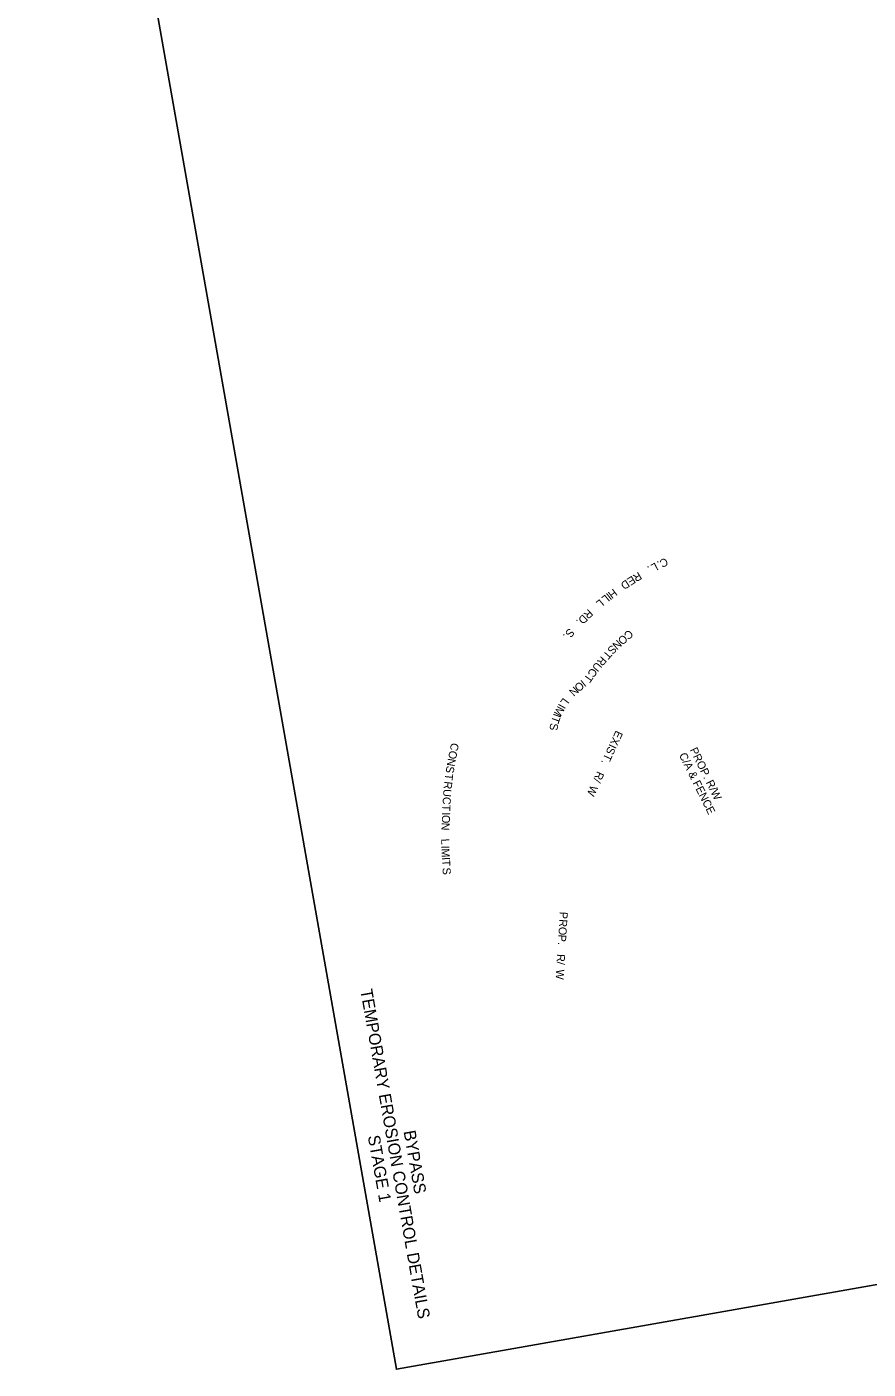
# Model space of a CAD drawing. Extents: x 979945 to 981206, y 1838799 to 1840551.
# Drawn here: x 979945 to 980575, y 1838799 to 1839805 of the extents above; entities that cross this region are included whole.
import ezdxf

# ---------------------------------------------------------------- set-up
doc = ezdxf.new("R2010")
doc.units = 0
for name, color, linetype in [('60', 7, 'Continuous'), ('Default', 7, 'Continuous'), ('R_Draft', 7, 'Continuous')]:
    doc.layers.add(name, color=color, linetype=linetype)

msp = doc.modelspace()

# ---------------------------------------------------------------- linework, layer by layer
at = {"layer": 'Default'}
msp.add_lwpolyline([(979944.5, 1840369.9), (980971, 1840550.9), (981196.2, 1839273.6), (981147.4, 1839265), (981177.1, 1839096.8), (981031.8, 1839071.2), (981054, 1838945.6), (980221.5, 1838798.8)], close=True, dxfattribs=at)

# ---------------------------------------------------------------- texts
at = {"layer": '60'}
for s, p in [('TEMPORARY EROSION CONTROL DETAILS', (980194.4, 1839083)), ('STAGE 1', (980200, 1838973.5)), ('BYPASS', (980226.8, 1838977.1))]:
    msp.add_text(s, height=9, rotation=280, dxfattribs=at).set_placement(p)
at = {"layer": 'R_Draft'}
for s, rotation, p in [('.', 206.8726, (980418.2, 1839405.1)), ('C', 205.4365, (980423.3, 1839407.5)), ('R', 211.2408, (980403, 1839396.9)), ('.', 208.9789, (980410.8, 1839401.3)), ('L', 207.6146, (980415.6, 1839403.8)), ('D', 214.0412, (980393.7, 1839391.1)), ('E', 212.6769, (980398.2, 1839394)), ('L', 220.2285, (980374, 1839376.6)), ('L', 218.8642, (980378.2, 1839380)), ('I', 218.3616, (980379.8, 1839381.2)), ('H', 216.9973, (980384.1, 1839384.4)), ('D', 224.5489, (980361.3, 1839365.2)), ('R', 223.1127, (980365.4, 1839369.1)), ('S', 228.2469, (980351.1, 1839354.8)), ('.', 225.985, (980357.2, 1839361.3)), ('.', 229.683, (980347.3, 1839350.6)), ('N', 221.5837, (980387.1, 1839346.1)), ('O', 221.5837, (980391.5, 1839350)), ('C', 220.5197, (980395.8, 1839353.7)), ('T', 228.7088, (980379, 1839338.2)), ('S', 226.1091, (980382.9, 1839342.3)), ('C', 234.6006, (980367.7, 1839325.1)), ('U', 230.7501, (980371.4, 1839329.5)), ('R', 228.7088, (980375.1, 1839333.8)), ('I', 218.7267, (980360.6, 1839316.1)), ('T', 234.6006, (980364.4, 1839320.5)), ('N', 224.6874, (980354.5, 1839311.2)), ('O', 218.7267, (980359.1, 1839314.8)), ('M', 240.8142, (980342.5, 1839296.5)), ('I', 240.8142, (980343.4, 1839298.3)), ('L', 233.18, (980346.6, 1839302.6)), ('T', 251.1039, (980338.8, 1839289)), ('I', 251.1039, (980339.4, 1839290.9)), ('S', 262.3723, (980336.9, 1839283.5)), ('E', 245.3622, (980386, 1839278.1)), ('C', 256.5166, (980262.7, 1839268.8)), ('S', 245.3622, (980380.5, 1839266.2)), ('I', 245.3622, (980381.3, 1839268)), ('X', 245.3622, (980383.7, 1839273.2)), ('PROP. R/W', 296.2946, (980441.2, 1839263.2)), ('N', 260.8024, (980260.1, 1839257.1)), ('O', 258.6823, (980261.4, 1839263)), ('.', 245.3622, (980375.7, 1839255.7)), ('T', 245.3622, (980378.1, 1839261)), ('C/A & FENCE', 296.2946, (980433.1, 1839259.3)), ('T', 263.7404, (980258.1, 1839245.6)), ('S', 260.8024, (980259.2, 1839251.5)), ('R', 245.3622, (980372, 1839247.6)), ('R', 263.7404, (980257.5, 1839239.8)), ('W', 245.3622, (980367.2, 1839237.1)), ('/', 245.3622, (980369.6, 1839242.4)), ('C', 266.3413, (980256.4, 1839228.1)), ('U', 266.3413, (980256.8, 1839233.9)), ('O', 268.299, (980255.7, 1839214.4)), ('I', 268.299, (980255.8, 1839216.4)), ('T', 268.299, (980256, 1839222.3)), ('N', 267.0066, (980255.5, 1839208.7)), ('L', 271.9356, (980255, 1839196.5)), ('I', 271.9356, (980255.2, 1839191.2)), ('M', 272.971, (980255.2, 1839189.1)), ('I', 272.971, (980255.6, 1839182.6)), ('T', 272.971, (980255.7, 1839180.7)), ('S', 273.8207, (980256, 1839174.7)), ('R', 266.507, (980343.6, 1839136.3)), ('P', 266.507, (980344, 1839141.9)), ('P', 266.507, (980342.9, 1839124.8)), ('O', 266.507, (980343.3, 1839130.6)), ('.', 266.507, (980342.6, 1839119.1)), ('/', 266.507, (980341.7, 1839104.5)), ('R', 266.507, (980342, 1839110.2)), ('W', 266.507, (980341.3, 1839098.7))]:
    msp.add_text(s, height=6, rotation=rotation, dxfattribs=at).set_placement(p)

doc.saveas('drawing.dxf')
